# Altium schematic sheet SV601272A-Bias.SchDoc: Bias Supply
size 431 x 279 mm; Date: Not shown in title block; ApprovedBy: Not shown in title block; CheckedBy: Not shown in title block; Author: Not shown in title block; CompanyName: Not shown in title block; Engineer: Not shown in title block; Organization: Not shown in title block; Address1: Not shown in title block; Address2: Not shown in title block; Address3: Not shown in title block; Address4: Not shown in title block; DocumentNumber: 3; Revision: Use project parameter SCH_Rev; SheetNumber: 3; SheetTotal: 11; PageSetup: Record=PageOptions¦CenterHorizontal=True¦CenterVertical=True¦PrintScale=1.00¦XCorrection=1.00¦YCorrection=1.00¦PrintKind=0¦BorderSize=5000000¦LeftOffset=0¦BottomOffset=0¦Orientation=2¦PaperLength=1000¦PaperWidth=1000¦Scale=100¦PaperSource=15¦PrintQuality=600¦MediaType=1¦DitherType=10¦PaperKind=Letter¦PrintScaleMode=1
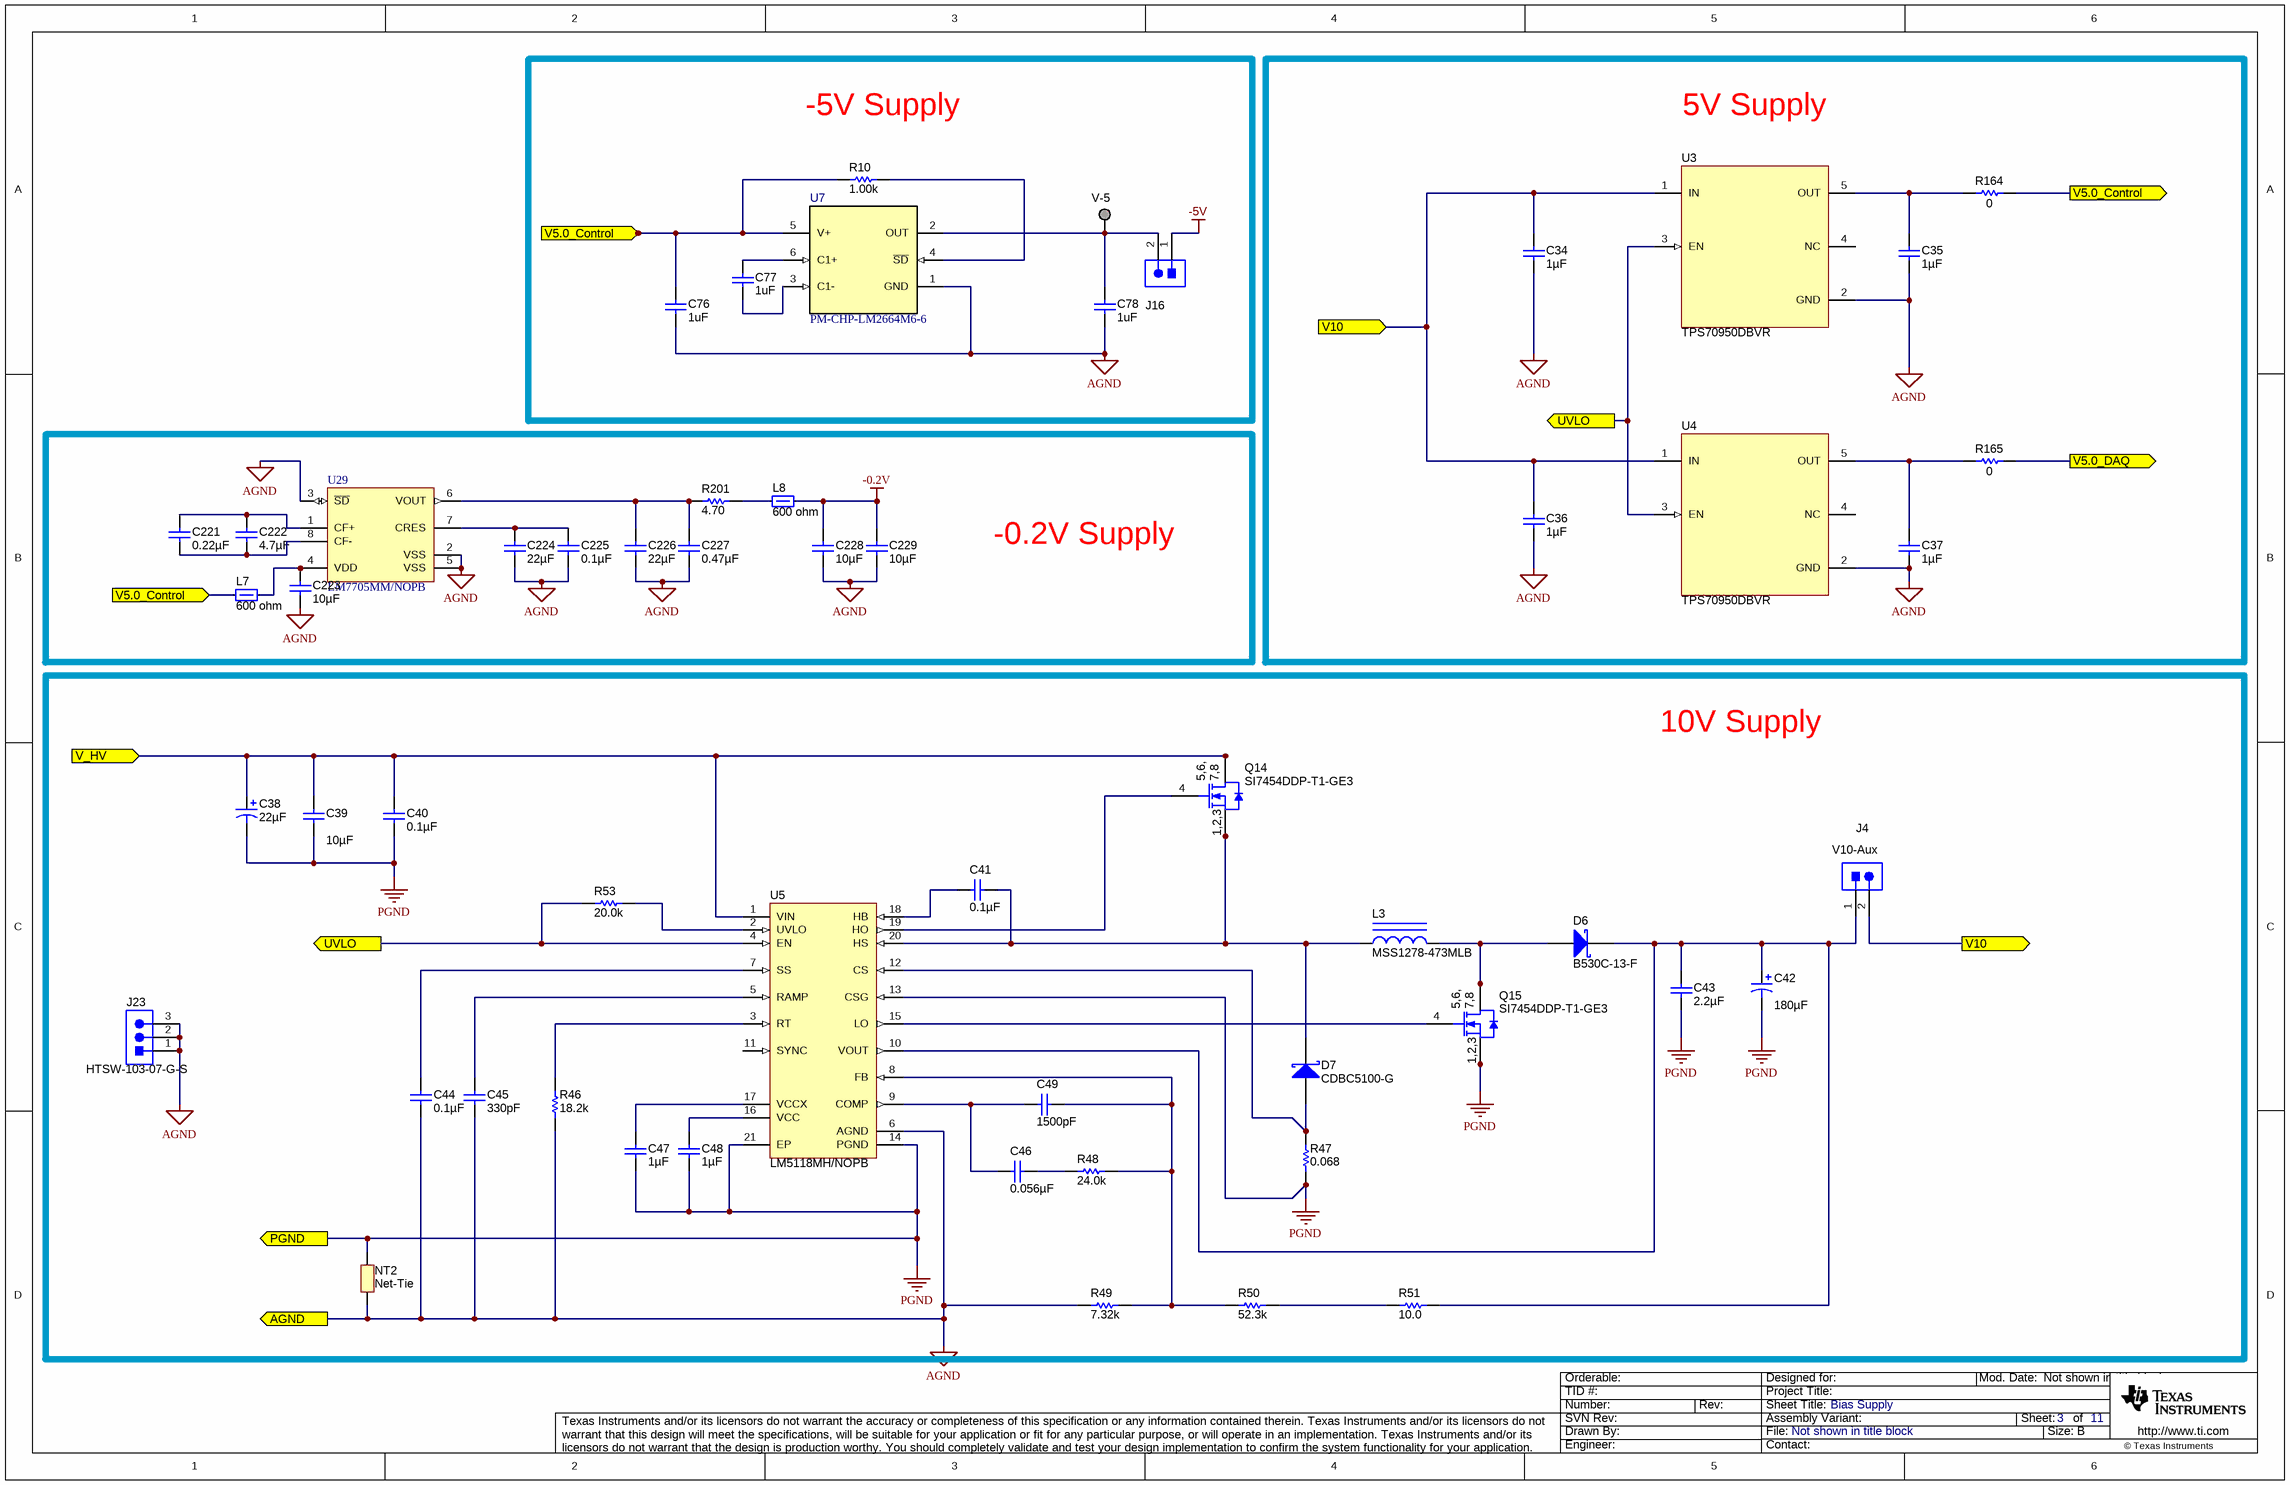
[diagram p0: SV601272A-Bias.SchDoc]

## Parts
C34  ValueDisplayed: 1µF  [0805_HV]  (hidden comment: C2012X7S2A105K125AB)
C35  ValueDisplayed: 1µF  [0805_HV]  (hidden comment: C2012X7S2A105K125AB)
C36  ValueDisplayed: 1µF  [0805_HV]  (hidden comment: C2012X7S2A105K125AB)
C37  ValueDisplayed: 1µF  [0805_HV]  (hidden comment: C2012X7S2A105K125AB)
C38  ValueDisplayed: 22µF  [CAPSMT_62_JA0]  (hidden comment: EMVH101ADA220MJA0G)
C39  ValueDisplayed: 10µF  [2220_250]  (hidden comment: C5750X7S2A106M230KB)
C40  ValueDisplayed: 0.1µF  [0805_HV]  (hidden comment: C2012X7R2A104K125AA)
C41  ValueDisplayed: 0.1µF  [0603L]  (hidden comment: GRM188R72A104KA35D)
C42  ValueDisplayed: 180µF  [CAPSMT_62_HC0]  (hidden comment: APXA160ARA181MHC0G)
C43  ValueDisplayed: 2.2µF  [0805_HV]  (hidden comment: C2012X7R1C225K125AB)
C44  ValueDisplayed: 0.1µF  [0603L]  (hidden comment: GRM188R72A104KA35D)
C45  ValueDisplayed: 330pF  [0603L]  (hidden comment: C1608C0G2A331J080AA)
C46  ValueDisplayed: 0.056µF  [0603L]  (hidden comment: GRM188R71H563KA93D)
C47  ValueDisplayed: 1µF  [0603L]  (hidden comment: GRM188R71E105KA12D)
C48  ValueDisplayed: 1µF  [0603L]  (hidden comment: GRM188R71E105KA12D)
C49  ValueDisplayed: 1500pF  [0603L]  (hidden comment: GRM1885C2A152JA01D)
C76  ValueDisplayed: 1uF  [0805_HV]  (hidden comment: Capacitor)
C77  ValueDisplayed: 1uF  [0805_HV]  (hidden comment: Capacitor)
C78  ValueDisplayed: 1uF  [0805_HV]  (hidden comment: Capacitor)
C221  ValueDisplayed: 0.22µF  [0603]  (hidden comment: GRM188R61A224KA01D)
C222  ValueDisplayed: 4.7µF  [0603]  (hidden comment: GRM188R61A475MAAJ)
C223  ValueDisplayed: 10µF  [0603]  (hidden comment: GRM188R61A106ME69D)
C224  ValueDisplayed: 22µF  [0603]  (hidden comment: GRM188R60J226MEA0D)
C225  ValueDisplayed: 0.1µF  [0603]  (hidden comment: GRM188R61C104KA01D)
C226  ValueDisplayed: 22µF  [0603]  (hidden comment: GRM188R60J226MEA0D)
C227  ValueDisplayed: 0.47µF  [0603]  (hidden comment: GRM188R71E474KA12D)
C228  ValueDisplayed: 10µF  [0603]  (hidden comment: GRM188R61A106ME69D)
C229  ValueDisplayed: 10µF  [0603]  (hidden comment: GRM188R61A106ME69D)
D6  B530C-13-F  [SMC]
D7  CDBC5100-G  [SMC]
J4  HTSW-102-07-G-S  [Samtec_HTSW-102-07-G-S]  (value not drawn)
J16  HTSW-102-07-G-S  [Samtec_HTSW-102-07-G-S]  (value not drawn)
J23  HTSW-103-07-G-S  [Samtec_HTSW-103-07-G-S]
L3  MSS1278-473MLB  [mss1278]
L7  value 600 ohm  [0805_HV]  (hidden comment: MPZ2012S601A)
L8  value 600 ohm  [0805_HV]  (hidden comment: MPZ2012S601A)
NT2  Net-Tie  [Net-Tie_10mil]  (net tie, no BOM)
Q14  SI7454DDP-T1-GE3  [PowerPAK_SO-8]
Q15  SI7454DDP-T1-GE3  [PowerPAK_SO-8]
R10  ValueDisplayed: 1.00k  [0603]  (hidden comment: ERJ-3EKF1001V)
R46  ValueDisplayed: 18.2k  [0603L]  (hidden comment: CRCW060318K2FKEA)
R47  ValueDisplayed: 0.068  [0612]  (hidden comment: PRL1632-R068-F-T1)
R48  ValueDisplayed: 24.0k  [0603L]  (hidden comment: RC0603FR-0724KL)
R49  ValueDisplayed: 7.32k  [0603]  (hidden comment: RC0603FR-077K32L)
R50  ValueDisplayed: 52.3k  [0603]  (hidden comment: RC0603FR-0752K3L)
R51  ValueDisplayed: 10.0  [0603L]  (hidden comment: CRCW060310R0FKEA)
R53  ValueDisplayed: 20.0k  [0603L]  (hidden comment: CRCW060320K0FKEA)
R164  ValueDisplayed: 0  [0603]  (hidden comment: Resistor)
R165  ValueDisplayed: 0  [0603]  (hidden comment: Resistor)
R201  ValueDisplayed: 4.70  [0603]  (hidden comment: RT0603DRE074R7L)
U3  TPS70950DBVR  [DBV0005A_N]
U4  TPS70950DBVR  [DBV0005A_N]
U5  LM5118MH/NOPB  [MXA20A_N]
U7  PM-CHP-LM2664M6-6  [DBV0006A_M]
U29  LM7705MM/NOPB  [MUA08A_N]
V-5  Pogo Pad  [PogoPad]  (value not drawn)  (no BOM)

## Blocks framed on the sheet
V10-Aux: C38-C49 D6 D7 J4 J23 L3 NT2 Q14 Q15 R46-R51 R53 U5

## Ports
AGND, PGND, UVLO, V5.0_Control, V5.0_DAQ, V10, V_HV

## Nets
-0.2V: C228.1 C229.1 L8.1
-5V: J16.1
AGND: C34.2 C35.2 C36.2 C37.2 C44.2 C45.2 C76.2 C78.2 C223.2 C224.2 C225.2 C226.2 C227.2 C228.2 C229.2 J23.1 J23.2 J23.3 NT2.1 R46.1 R49.1 U3.2(GND) U4.2(GND) U5.6(AGND) U7.1(GND) U29.2(VSS) U29.3(~{SD}) U29.5(VSS) ; port AGND
PGND: C38.2(-) C39.2 C40.2 C42.2(-) C43.2 C47.2 C48.2 NT2.2 Q15.1(S) Q15.2(S) Q15.3(S) R47.1 U5.13(CSG) U5.14(PGND) U5.21(EP) ; port PGND
UVLO: R53.1 U3.3(EN) U4.3(EN) U5.4(EN) ; port UVLO
V5.0_Control: C76.1 L7.2 R10.1 R164.2 U7.5(V+) ; port V5.0_Control
V5.0_DAQ: R165.2 ; port V5.0_DAQ
V10: C34.1 C36.1 J4.2 U3.1(IN) U4.1(IN) ; port V10
V_HV: C38.1(+) C39.1 C40.1 Q14.5(D) Q14.6(D) Q14.7(D) Q14.8(D) Q14.9(D) U5.1(VIN) ; port V_HV
NetC35_1: C35.1 R164.1 U3.5(OUT)
NetC37_1: C37.1 R165.1 U4.5(OUT)
NetC41_1: C41.1 D7.1(K) L3.1 Q14.1(S) Q14.2(S) Q14.3(S) U5.20(HS)
NetC41_2: C41.2 U5.18(HB)
NetC42_1: C42.1(+) C43.1 D6.1(K) J4.1 R51.2 U5.10(VOUT)
NetC44_1: C44.1 U5.7(SS)
NetC45_1: C45.1 U5.5(RAMP)
NetC46_1: C46.1 C49.1 U5.9(COMP)
NetC46_2: C46.2 R48.2
NetC47_1: C47.1 U5.17(VCCX)
NetC48_1: C48.1 U5.16(VCC)
NetC49_2: C49.2 R48.1 R49.2 R50.1 U5.8(FB)
NetC77_1: C77.1 U7.6(C1+)
NetC77_2: C77.2 U7.3(C1-)
NetC78_1: C78.1 J16.2 U7.2(OUT) V-5.1
NetC221_1: C221.1 C222.1 U29.1(CF+)
NetC221_2: C221.2 C222.2 U29.8(CF-)
NetC223_1: C223.1 L7.1 U29.4(VDD)
NetC224_1: C224.1 C225.1 U29.7(CRES)
NetC226_1: C226.1 C227.1 R201.1 U29.6(VOUT)
NetD6_2: D6.2(A) L3.2 Q15.5(D) Q15.6(D) Q15.7(D) Q15.8(D) Q15.9(D)
NetD7_2: D7.2(A) R47.2 U5.12(CS)
NetL8_2: L8.2 R201.2
NetQ14_4: Q14.4(G) U5.19(HO)
NetQ15_4: Q15.4(G) U5.15(LO)
NetR10_2: R10.2 U7.4(~{SD})
NetR46_2: R46.2 U5.3(RT)
NetR50_2: R50.2 R51.1
NetR53_2: R53.2 U5.2(UVLO)

Not connected (* = marked no-connect by the designer): U3 4(NC); U4 4(NC); U5 11(SYNC)

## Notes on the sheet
- -5V Supply
- 5V Supply
- -0.2V Supply
- 10V Supply

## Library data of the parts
C34-C37 = C2012X7S2A105K125AB: CAP, CERM, 1 µF, 100 V, +/- 10%, X7S, 0805; Manufacturer: TDK; Polarized: N; CompType: Capacitor; Value: 1uF; U/M: EA; Cap_F: 0.000001; Tolerance_%: 10; Value1: Unknown; VDC_V: 100; Value2: 100V; TaMin_C: -55; TaMax_C: 125; Cap_Case: 0805; AEC Category: Q200
C38 = EMVH101ADA220MJA0G: CAP, AL, 22 µF, 100 V, +/- 20%, 0.55 ohm, SMD; Manufacturer: Chemi-Con; Polarized: Y; CompType: Capacitor; Value: 22uF; U/M: EA; Cap_F: 0.000022; Tolerance_%: 20; VDC_V: 100; Value2: 100V; ESR_ohm: 0.55; IRMS_A: 0.115; TaMin_C: -40; TaMax_C: 125; Cap_Case: JA0
C39 = C5750X7S2A106M230KB: CAP, CERM, 10 µF, 100 V, +/- 20%, X7S,; Manufacturer: TDK; Polarized: N; CompType: Capacitor; Value: 10uF; U/M: EA; Cap_F: 0.00001; Tolerance_%: 20; ESR_ohm: 0.005; Value1: 0.005 ohm; VDC_V: 100; Value2: 100V; IRMS_A: 6.45; TaMin_C: -55; TaMax_C: 125; Cap_Case: 2220; SizeArea_mm2: 28.5; SizeAreaWB_mm2: 53.9; SizeX_mm: 5.7; SizeY_mm: 5; SizeZ_mm: 2.5; AEC Category: Q200
C40 = C2012X7R2A104K125AA: CAP, CERM, 0.1 µF, 100 V, +/- 10%, X7R, 0805; Manufacturer: TDK; Polarized: N; CompType: Capacitor; Value: 0.1uF; U/M: EA; Cap_F: 0.0000001; Tolerance_%: 10; ESR_ohm: 0.0158; Value1: 0.0158 ohm; VDC_V: 100; Value2: 100V; TaMin_C: -55; TaMax_C: 125; Cap_Case: 0805; AEC Category: Q200
C41 C44 = GRM188R72A104KA35D: CAP, CERM, 0.1 µF, 100 V, +/- 10%, X7R, 0603; Manufacturer: MuRata; Polarized: N; CompType: Capacitor; Value: 0.1uF; U/M: EA; Cap_F: 0.0000001; Tolerance_%: 10; Value1: Unknown; VDC_V: 100; Value2: 100V; TaMin_C: -55; TaMax_C: 125; Cap_Case: 0603; AEC Category: Q200
C42 = APXA160ARA181MHC0G: CAP, Aluminum Polymer, 180 µF, 16 V, +/- 20%, 0.016 ohm, HC0 SMD; Manufacturer: Chemi-Con; Polarized: Y; CompType: Capacitor; Value: 180uF; U/M: EA; Cap_F: 0.00018; Tolerance_%: 20; VDC_V: 16; Value2: 16V; ESR_ohm: 0.016; IRMS_A: 4.36; TaMin_C: -55; TaMax_C: 105; SizeAreaWB_mm2: 110.25; SizeArea_mm2: 72.25; SizeX_mm: 8.5; SizeZ_mm: 12.3; AEC Category: Q200; AEC Qualified: N
C43 = C2012X7R1C225K125AB: CAP, CERM, 2.2 µF, 16 V, +/- 10%, X7R, 0805; Manufacturer: TDK; Polarized: N; CompType: Capacitor; Value: 2.2uF; U/M: EA; Cap_F: 0.0000022; Tolerance_%: 10; ESR_ohm: 0.0049; Value1: 0.0049 ohm; VDC_V: 16; Value2: 16V; TaMin_C: -55; TaMax_C: 125; Cap_Case: 0805; AEC Category: Q200
C45 = C1608C0G2A331J080AA: CAP, CERM, 330 pF, 100 V, +/- 5%, C0G/NP0, 0603; Manufacturer: TDK; Polarized: N; CompType: Capacitor; Value: 330pF; U/M: EA; Cap_F: 0.00000000033; Tolerance_%: 5; ESR_ohm: 0.1269; Value1: 0.1269 ohm; VDC_V: 100; Value2: 100V; TaMin_C: -55; TaMax_C: 125; Cap_Case: 0603; AEC Category: Q200
C46 = GRM188R71H563KA93D: CAP, CERM, 0.056 µF, 50 V, +/- 10%, X7R, 0603; Manufacturer: MuRata; Polarized: N; CompType: Capacitor; Value: 0.056uF; U/M: EA; Cap_F: 0.000000056; Tolerance_%: 10; Value1: Unknown; VDC_V: 50; Value2: 50V; TaMin_C: -55; TaMax_C: 125; Cap_Case: 0603
C47 C48 = GRM188R71E105KA12D: CAP, CERM, 1 µF, 25 V, +/- 10%, X7R, 0603; Manufacturer: MuRata; Polarized: N; CompType: Capacitor; Value: 1uF; U/M: EA; Cap_F: 0.000001; Tolerance_%: 10; Value1: Unknown; VDC_V: 25; Value2: 25V; TaMin_C: -55; TaMax_C: 125; Cap_Case: 0603
C49 = GRM1885C2A152JA01D: CAP, CERM, 1500 pF, 100 V, +/- 5%, C0G/NP0, 0603; Manufacturer: MuRata; Polarized: N; CompType: Capacitor; Value: 1500pF; U/M: EA; Cap_F: 0.0000000015; Tolerance_%: 5; Value1: Unknown; VDC_V: 100; Value2: 100V; TaMin_C: -55; TaMax_C: 125; Cap_Case: 0603
C76-C78 = CMP-0007891-2: CAP, CERM, 1 uF, 100 V, +/- 10%, X7S, 0805; PartNumber: C2012X7S2A105K125AB; Manufacturer: TDK; Polarized: N; Value: 1uF; U/M: EA; Cap_F: 1µF; ESR_ohm: 8.255m; Value1: 0.008255 ohm; VDC_V: 100V; IRMS_A: 2.27442A; TaMin_C: -55°C; TaMax_C: 125°C; Cap_Case: 0805; AEC Category: Q200; SizeArea_mm2: 2.5; SizeAreaWB_mm2: 6.75; SizeX_mm: 2; SizeY_mm: 1.25; SizeZ_mm: 1.45
C221 = GRM188R61A224KA01D: CAP, CERM, 0.22 µF, 10 V, +/- 10%, X5R, 0603; Manufacturer: MuRata; Polarized: N; CompType: Capacitor; Value: 0.22uF; U/M: EA; Cap_F: 0.00000022; Tolerance_%: 10; Value1: Unknown; Value2: 10V; TaMin_C: -55; TaMax_C: 85; SizeArea_mm2: 1.28; SizeAreaWB_mm2: 4.68; SizeX_mm: 1.6; SizeY_mm: 0.8; SizeZ_mm: 1; AEC Category: Q200
C222 = GRM188R61A475MAAJ: CAP, CERM, 4.7 µF, 10 V, +/- 20%, X5R, 0603; Manufacturer: MuRata; Polarized: N; CompType: Capacitor; Value: 4.7uF; U/M: EA; Cap_F: 0.0000047; Tolerance_%: 20; Value1: Unknown; VDC_V: 10; Value2: 10V; TaMin_C: -55; TaMax_C: 85; SizeArea_mm2: 1.28; SizeAreaWB_mm2: 4.68; SizeX_mm: 1.6; SizeY_mm: 0.8; SizeZ_mm: 1; AEC Category: Q200
C223 C228 C229 = GRM188R61A106ME69D: CAP, CERM, 10 µF, 10 V, +/- 20%, X5R, 0603; Manufacturer: MuRata; Polarized: N; CompType: Capacitor; Value: 10uF; U/M: EA; Cap_F: 0.00001; Tolerance_%: 20; Value1: Unknown; VDC_V: 10; Value2: 10V; TaMin_C: -55; TaMax_C: 85; SizeArea_mm2: 1.28; SizeAreaWB_mm2: 4.68; SizeX_mm: 1.6; SizeY_mm: 0.8; SizeZ_mm: 1; AEC Category: Q200
C224 C226 = GRM188R60J226MEA0D: CAP, CERM, 22 µF, 6.3 V, +/- 20%, X5R, 0603; Manufacturer: MuRata; Polarized: N; CompType: Capacitor; Value: 22uF; U/M: EA; Cap_F: 0.000022; Tolerance_%: 20; Value1: Unknown; VDC_V: 6.3; Value2: 6.3V; TaMin_C: -55; TaMax_C: 85; SizeArea_mm2: 1.28; SizeAreaWB_mm2: 4.68; SizeX_mm: 1.6; SizeY_mm: 0.8; SizeZ_mm: 1; AEC Category: Q200
C225 = GRM188R61C104KA01D: CAP, CERM, 0.1 µF, 16 V, +/- 10%, X5R, 0603; Manufacturer: MuRata; Polarized: N; CompType: Capacitor; Value: 0.1uF; U/M: EA; Cap_F: 0.0000001; Tolerance_%: 10; Value1: Unknown; VDC_V: 16; Value2: 16V; TaMin_C: -55; TaMax_C: 85; SizeArea_mm2: 1.28; SizeAreaWB_mm2: 4.68; SizeX_mm: 1.6; SizeY_mm: 0.8; SizeZ_mm: 1; AEC Category: Q200
C227 = GRM188R71E474KA12D: CAP, CERM, 0.47 µF, 25 V, +/- 10%, X7R, 0603; Manufacturer: MuRata; Polarized: N; CompType: Capacitor; Value: 0.47uF; U/M: EA; Cap_F: 0.00000047; Tolerance_%: 10; Value1: Unknown; VDC_V: 25; Value2: 25V; TaMin_C: -55; TaMax_C: 125; SizeArea_mm2: 1.28; SizeAreaWB_mm2: 4.68; SizeX_mm: 1.6; SizeY_mm: 0.8; SizeZ_mm: 1; AEC Category: Q200
D6 = B530C-13-F: Diode, Schottky, 30 V, 5 A, SMC; Manufacturer: Diodes Inc.; U/M: EA; Vf_V: 0.55; Value: 30V; Value1: 5A; Value2: 0.55V; Io_A: 5; Vr_V: 30; TJmax_C: 125; RJC_CperW: 10
D7 = CDBC5100-G: Diode, Schottky, 100 V, 5 A, SMC; Manufacturer: Comchip Technology; U/M: EA; Vf_V: 0.85; Value: 100V; Value1: 5A; Value2: 0.85V; Io_A: 5; Vr_V: 100; TJmax_C: 125
J4 J16 = HTSW-102-07-G-S: Header, 100mil, 2x1, Gold, TH; Manufacturer: Samtec; SymbolCreator: a0412235; U/M: EA
J23 = HTSW-103-07-G-S: Header, 100mil, 3x1, Gold, TH; Manufacturer: Samtec; SymbolCreator: a0799628; U/M: EA
L3 = MSS1278-473MLB: Inductor, Shielded Drum Core, Ferrite, 47 µH, 2.9 A, 0.07 ohm, SMD; Manufacturer: Coilcraft; Value: 47uH; Ind_H: 47.0E-6; ValueDisplayed: 47µH; Imax_A: 2.9; Irms: 2.9A @ 40C rise; Isat: 5.32A @ 30% inductance drop; DCR_ohm: 0.07; Value2: 2.9A
L7 L8 = MPZ2012S601A: Ferrite Bead, 600 ohm @ 100MHz, 2A, 0805; Manufacturer: TDK; Imax_A: 2; DCR_ohm: 0.1; Value1: 0.1 ohm; ZTyp@100MHz_Ohm: 600
NT2 = Net-Tie: Single point connection between nets.; SymbolCreator: codlsc
Q14 Q15 = SI7454DDP-T1-GE3: MOSFET, N-CH, 100 V, 21 A, PowerPAK SO-8; Manufacturer: Vishay-Siliconix; Alternate Manufacturer: None; U/M: EA; ChType: N; Value: 100V; VdsMax_V: 100; Value1: 0.047 ohm; Rdson45_ohm: 0.047; Value2: 12.8 nC; QgTyp_nC: 12.8; Vgs_V: 20; IdsMax_A: 21; SizeAreaWB_mm2: 55.131; SizeArea_mm2: 29.351; SizeX_mm: 5.99; SizeY_mm: 4.9; SizeZ_mm: 1.12; AEC Category: Q101
R10 = CMP-0022680-4: RES, 1.00 k, 1%, 0.1 W, 0603; Manufacturer: Panasonic; Power_W: 100mW; TempCo: 100 ppm/C; Value_Code: 1k00; U/M: EA; Value: 1.00k; EIA_Code: E96; Res_ohm: 1k; SizeX_mm: 1.6; SizeY_mm: 0.8; SizeZ_mm: 1; SizeArea_mm2: 1.28; CompType: Resistor; VDC_V: 75V; AEC Category: Q200; Value2: 0.1W
R46 = CRCW060318K2FKEA: RES, 18.2 k, 1%, 0.1 W, 0603; Manufacturer: Vishay-Dale; CompType: Resistor; Value: 18.2k; Res_ohm: 18200; Value_Code: 18k2; Tolerance_%: 1; Power_W: 0.1; Value2: 0.1W; VDC_V: 75; TempCo: 100 ppm/C; EIA_Code: E96; U/M: EA
R47 = PRL1632-R068-F-T1: RES, 0.068, 1%, 1 W, 0612; Manufacturer: Susumu Co Ltd; CompType: Resistor; Value: 0.068; Value_Code: R068; Tolerance_%: 1; Value2: 1W; TempCo: 50 ppm/C; U/M: EA
R48 = RC0603FR-0724KL: RES, 24.0 k, 1%, 0.1 W, 0603; Manufacturer: Yageo America; CompType: Resistor; Value: 24.0k; Res_ohm: 24000; Value_Code: 24k0; Tolerance_%: 1; Power_W: 0.1; Value2: 0.1W; VDC_V: 150; TempCo: 200 ppm/C; U/M: EA
R49 = CMP-0023278-3: RES, 7.32 k, 1%, 0.1 W, 0603; Manufacturer: Yageo America; Power_W: 100mW; TempCo: 200 ppm/C; Value_Code: 7k32; U/M: EA; Value: 7.32k; EIA_Code: E96; SizeX_mm: 1.6; SizeY_mm: 0.8; SizeZ_mm: 1; Value2: 0.1W; SizeArea_mm2: 1.28; CompType: Resistor; VDC_V: 150V; AEC Category: Q200
R50 = CMP-0023172-3: RES, 52.3 k, 1%, 0.1 W, 0603; Manufacturer: Yageo America; Power_W: 100mW; TempCo: 200 ppm/C; Value_Code: 52k3; U/M: EA; Value: 52.3k; EIA_Code: E96; SizeX_mm: 1.6; SizeY_mm: 0.8; SizeZ_mm: 1; Value2: 0.1W; SizeArea_mm2: 1.28; CompType: Resistor; VDC_V: 150V; AEC Category: Q200
R51 = CRCW060310R0FKEA: RES, 10.0, 1%, 0.1 W, 0603; Manufacturer: Vishay-Dale; CompType: Resistor; Value: 10.0; Res_ohm: 10; Value_Code: 10R0; Tolerance_%: 1; Power_W: 0.1; Value2: 0.1W; VDC_V: 75; TempCo: 100 ppm/C; EIA_Code: E96; U/M: EA
R53 = CRCW060320K0FKEA: RES, 20.0 k, 1%, 0.1 W, 0603; Manufacturer: Vishay-Dale; CompType: Resistor; Value: 20.0k; Res_ohm: 20000; Value_Code: 20k0; Tolerance_%: 1; Power_W: 0.1; Value2: 0.1W; VDC_V: 75; TempCo: 100 ppm/C; EIA_Code: E96; U/M: EA; AEC Category: Q200
R164 R165 = CMP-0025874-3: RES, 0, 5%, 0.1 W, 0603; PartNumber: ERJ-3GEY0R00V; Manufacturer: Panasonic; Value: 0; Value_Code: 0000; Power_W: 100mW; Value2: 0.1W; VDC_V: 50V; TempCo: 600 ppm/C; EIA_Code: E24; U/M: EA; AEC Category: Q200; SizeArea_mm2: 1.28; SizeX_mm: 1.6; SizeY_mm: 0.8; SizeZ_mm: 1
R201 = RT0603DRE074R7L: RES, 4.70, 0.5%, 0.1 W, 0603; Manufacturer: Yageo America; CompType: Resistor; Value: 4.70; Res_ohm: 4.7; Value_Code: 4R70; Tolerance_%: 0.5; Power_W: 0.1; Value2: 0.1W; VDC_V: 75; TempCo: 50 ppm/C; SizeArea_mm2: 1.28; SizeX_mm: 1.6; SizeY_mm: 0.8; SizeZ_mm: 1; EIA_Code: E192; U/M: EA; AEC Category: Q200
U3 U4 = TPS70950DBVR: 150-mA, 30-V, 1-uA IQ Voltage Regulators with Enable, DBV0005A; Alternate PartNumber: TPS70950DBVT; Manufacturer: Texas Instruments; SymbolCreator: Altium; CompType: IC; U/M: EA
U5 = LM5118MH/NOPB: Wide Voltage Range Buck-Boost Controller, 20-pin TSSOP-EP, Pb-Free; Manufacturer: Texas Instruments; PackageTopMarking: NSUZXYTT*LM5118*MH; PowerWise: Y; CompType: Switcher
U7 = CMP-0072146-1: Switched Capacitor Voltage Converter, 6-pin SOT-23; Manufacturer: Texas Instruments; PackageTopMarking: S03A*XTT; PowerWise: N; CompType: Switch Caps
U29 = LM7705MM/NOPB: Low Noise Negative Bias Generator, 8-pin Mini SOIC, Pb-Free; Manufacturer: Texas Instruments; PackageTopMarking: ZXTT*F26A; PowerWise: N; CompType: OtherParts
V-5 = PogoPad: Pad for Pogo Pin Connector; SymbolCreator: codlsc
